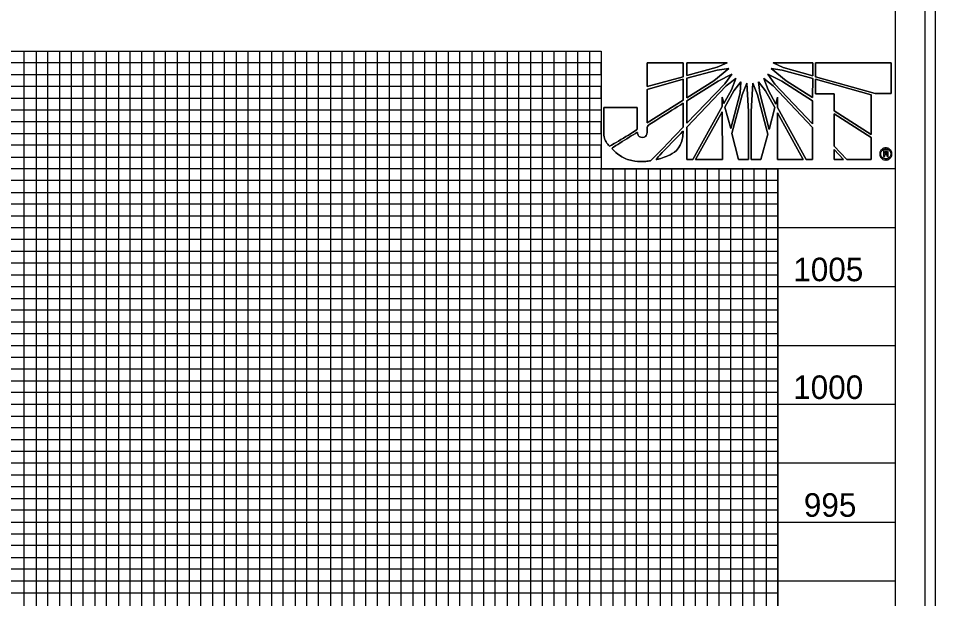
# Model space of a CAD drawing. Extents: x 0 to 4772457, y -312190 to 1506.
# Drawn here: x 2.184 to 2.833, y 0.492 to 0.902 of the extents above; entities that cross this region are included whole.
import ezdxf

# ---------------------------------------------------------------- set-up
doc = ezdxf.new("R2010")
doc.units = 0
for name, color, linetype in [('Exist Curb and Gutter', 7, 'Continuous'), ('Exist Mini Skip Lane Lines', 7, 'Continuous'), ('Legend CELL', 7, 'Continuous'), ('Old_Level_38', 7, 'Continuous'), ('Old_Level_57', 7, 'Continuous'), ('Old_Level_63', 7, 'Continuous')]:
    doc.layers.add(name, color=color, linetype=linetype)

# ---------------------------------------------------------------- blocks, each defined once
blk = doc.blocks.new('block 2_1')
at = {"layer": 'Exist Curb and Gutter'}
for p, q in [((0.10682, 0.1325), (0.10682, 0.14026)), ((0.10682, 0.14026), (0.11852, 0.14026)), ((0.11852, 0.14026), (0.11852, 0.13575)), ((0.11973, 0.13613), (0.11973, 0.14032)), ((0.11973, 0.14032), (0.1329, 0.14032)), ((0.12954, 0.13884), (0.11973, 0.13613)), ((0.11973, 0.13523), (0.12954, 0.13793)), ((0.13337, 0.13839), (0.12852, 0.13445)), ((0.1329, 0.14032), (0.12954, 0.13884)), ((0.12954, 0.13793), (0.13337, 0.13839)), ((0.14715, 0.13839), (0.15076, 0.13793)), ((0.15206, 0.13438), (0.14715, 0.13839)), ((0.15109, 0.13878), (0.14781, 0.14032)), ((0.14781, 0.14032), (0.16078, 0.14026)), ((0.15076, 0.13793), (0.16078, 0.13517)), ((0.16078, 0.13606), (0.15109, 0.13878)), ((0.16078, 0.14026), (0.16078, 0.13606)), ((0.16169, 0.1358), (0.16169, 0.14032)), ((0.16169, 0.14032), (0.18629, 0.14032)), ((0.18629, 0.14032), (0.18629, 0.13024)), ((0.11852, 0.13575), (0.10682, 0.1325)), ((0.10682, 0.13161), (0.11852, 0.1349)), ((0.11852, 0.1349), (0.11852, 0.12812)), ((0.11973, 0.12889), (0.11973, 0.13523)), ((0.12987, 0.13432), (0.13433, 0.13658)), ((0.13433, 0.13658), (0.13207, 0.13341)), ((0.13257, 0.13277), (0.13568, 0.13517)), ((0.13568, 0.13517), (0.13425, 0.13142)), ((0.14476, 0.13517), (0.14787, 0.13277)), ((0.14619, 0.13142), (0.14476, 0.13517)), ((0.14613, 0.13658), (0.15065, 0.13432)), ((0.14839, 0.13335), (0.14613, 0.13658)), ((0.16078, 0.13517), (0.16071, 0.12897)), ((0.16169, 0.13567), (0.16169, 0.1358)), ((0.18106, 0.13024), (0.16169, 0.13567)), ((0.16169, 0.13497), (0.17982, 0.1298)), ((0.16169, 0.1349), (0.16169, 0.13497)), ((0.16169, 0.13019), (0.16169, 0.1349)), ((0.10682, 0.12071), (0.10682, 0.13161)), ((0.12852, 0.13445), (0.11973, 0.12889)), ((0.11973, 0.12787), (0.12987, 0.13432)), ((0.13207, 0.13341), (0.11973, 0.12057)), ((0.11973, 0.11933), (0.13257, 0.13277)), ((0.13505, 0.13115), (0.13736, 0.13412)), ((0.13736, 0.13412), (0.13704, 0.13051)), ((0.13769, 0.12986), (0.13929, 0.1336)), ((0.13929, 0.1336), (0.1398, 0.12437)), ((0.14063, 0.12437), (0.14123, 0.1336)), ((0.14123, 0.1336), (0.14277, 0.12986)), ((0.1431, 0.13412), (0.14536, 0.13115)), ((0.14348, 0.13038), (0.1431, 0.13412)), ((0.14787, 0.13277), (0.16071, 0.11922)), ((0.16071, 0.12043), (0.14839, 0.13335)), ((0.15065, 0.13432), (0.16071, 0.12793)), ((0.16071, 0.12897), (0.15206, 0.13438)), ((0.1318, 0.12696), (0.13122, 0.12908)), ((0.13122, 0.12908), (0.13122, 0.126)), ((0.13425, 0.13142), (0.1318, 0.12696)), ((0.13213, 0.12586), (0.13505, 0.13115)), ((0.13704, 0.13051), (0.134, 0.11883)), ((0.13439, 0.11721), (0.13769, 0.12986)), ((0.14277, 0.12986), (0.14613, 0.11702)), ((0.14652, 0.11856), (0.14348, 0.13038)), ((0.14536, 0.13115), (0.14839, 0.12567)), ((0.1487, 0.12677), (0.14619, 0.13142)), ((0.1493, 0.12908), (0.1487, 0.12677)), ((0.1493, 0.12567), (0.1493, 0.12908)), ((0.1677, 0.13019), (0.16169, 0.13019)), ((0.1677, 0.12457), (0.1677, 0.13019)), ((0.17982, 0.1298), (0.17982, 0.11688)), ((0.18629, 0.13024), (0.18106, 0.13024)), ((0.11852, 0.12812), (0.10682, 0.12071)), ((0.11973, 0.12057), (0.11973, 0.12787)), ((0.13122, 0.126), (0.12167, 0.10871)), ((0.134, 0.11883), (0.13213, 0.12586)), ((0.14839, 0.12567), (0.14652, 0.11856)), ((0.15864, 0.10871), (0.1493, 0.12567)), ((0.16071, 0.12793), (0.16071, 0.12043)), ((0.12257, 0.10871), (0.13122, 0.12432)), ((0.13122, 0.12432), (0.1313, 0.10871)), ((0.1398, 0.12437), (0.1398, 0.10877)), ((0.14063, 0.10877), (0.14063, 0.12437)), ((0.1493, 0.10877), (0.1493, 0.12399)), ((0.1493, 0.12399), (0.15768, 0.10877)), ((0.17982, 0.11688), (0.1677, 0.12457)), ((0.1677, 0.1236), (0.17982, 0.11597)), ((0.1677, 0.11314), (0.1677, 0.1236)), ((0.11973, 0.10871), (0.11973, 0.11933)), ((0.13659, 0.10877), (0.13439, 0.11721)), ((0.14613, 0.11702), (0.14387, 0.10877)), ((0.16071, 0.11922), (0.16071, 0.10871)), ((0.17982, 0.11597), (0.17982, 0.10871)), ((0.17189, 0.10871), (0.1677, 0.11314)), ((0.1677, 0.10871), (0.1677, 0.112)), ((0.1677, 0.112), (0.17073, 0.10871)), ((0.12167, 0.10871), (0.11973, 0.10871)), ((0.1313, 0.10871), (0.12257, 0.10871)), ((0.1398, 0.10877), (0.13659, 0.10877)), ((0.14387, 0.10877), (0.14063, 0.10877)), ((0.15768, 0.10877), (0.1493, 0.10877)), ((0.16071, 0.10871), (0.15864, 0.10871)), ((0.17073, 0.10871), (0.1677, 0.10871)), ((0.17982, 0.10871), (0.17189, 0.10871))]:
    blk.add_line(p, q, dxfattribs=at)
for points in [[(0.10682, 0.1325), (0.11852, 0.13575), (0.11852, 0.14026), (0.10682, 0.14026), (0.10682, 0.1325)], [(0.12954, 0.13884), (0.1329, 0.14032), (0.11973, 0.14032), (0.11973, 0.13613), (0.12954, 0.13884)], [(0.11973, 0.13523), (0.11973, 0.12889), (0.12852, 0.13445), (0.13337, 0.13839), (0.12954, 0.13793), (0.11973, 0.13523)], [(0.14715, 0.13839), (0.15206, 0.13438), (0.16071, 0.12897), (0.16078, 0.13517), (0.15076, 0.13793), (0.14715, 0.13839)], [(0.15109, 0.13878), (0.16078, 0.13606), (0.16078, 0.14026), (0.14781, 0.14032), (0.15109, 0.13878)], [(0.18629, 0.14032), (0.16169, 0.14032), (0.16169, 0.1358), (0.16169, 0.13567), (0.18106, 0.13024), (0.18629, 0.13024), (0.18629, 0.14032)], [(0.10682, 0.12071), (0.11852, 0.12812), (0.11852, 0.1349), (0.10682, 0.13161), (0.10682, 0.12071)], [(0.11973, 0.12787), (0.11973, 0.12057), (0.13207, 0.13341), (0.13433, 0.13658), (0.12987, 0.13432), (0.11973, 0.12787)], [(0.13568, 0.13517), (0.13257, 0.13277), (0.11973, 0.11933), (0.11973, 0.10871), (0.12167, 0.10871), (0.13122, 0.126), (0.13122, 0.12908), (0.1318, 0.12696), (0.13425, 0.13142), (0.13568, 0.13517)], [(0.14476, 0.13517), (0.14619, 0.13142), (0.1487, 0.12677), (0.1493, 0.12908), (0.1493, 0.12567), (0.15864, 0.10871), (0.16071, 0.10871), (0.16071, 0.11922), (0.14787, 0.13277), (0.14476, 0.13517)], [(0.14613, 0.13658), (0.14839, 0.13335), (0.16071, 0.12043), (0.16071, 0.12793), (0.15065, 0.13432), (0.14613, 0.13658)], [(0.16169, 0.13497), (0.16169, 0.1349), (0.16169, 0.13019), (0.1677, 0.13019), (0.1677, 0.12457), (0.17982, 0.11688), (0.17982, 0.1298), (0.16169, 0.13497)], [(0.13736, 0.13412), (0.13505, 0.13115), (0.13213, 0.12586), (0.134, 0.11883), (0.13704, 0.13051), (0.13736, 0.13412)], [(0.13769, 0.12986), (0.13439, 0.11721), (0.13659, 0.10877), (0.1398, 0.10877), (0.1398, 0.12437), (0.13929, 0.1336), (0.13769, 0.12986)], [(0.14123, 0.1336), (0.14063, 0.12437), (0.14063, 0.10877), (0.14387, 0.10877), (0.14613, 0.11702), (0.14277, 0.12986), (0.14123, 0.1336)], [(0.1431, 0.13412), (0.14348, 0.13038), (0.14652, 0.11856), (0.14839, 0.12567), (0.14536, 0.13115), (0.1431, 0.13412)], [(0.12257, 0.10871), (0.1313, 0.10871), (0.13122, 0.12432), (0.12257, 0.10871)], [(0.1493, 0.10877), (0.15768, 0.10877), (0.1493, 0.12399), (0.1493, 0.10877)], [(0.1677, 0.1236), (0.1677, 0.11314), (0.17189, 0.10871), (0.17982, 0.10871), (0.17982, 0.11597), (0.1677, 0.1236), (0.1677, 0.1236)], [(0.1677, 0.10871), (0.1677, 0.10871), (0.17073, 0.10871), (0.1677, 0.112), (0.1677, 0.10871)], [(0.18456, 0.11147), (0.18383, 0.11147), (0.18383, 0.10968), (0.18424, 0.10968), (0.18424, 0.11038), (0.18456, 0.11038), (0.18456, 0.1107), (0.18424, 0.1107), (0.18424, 0.11113), (0.18456, 0.11113), (0.18456, 0.11147)], [(0.18456, 0.11147), (0.18383, 0.11147), (0.18383, 0.10968), (0.18424, 0.10968), (0.18424, 0.11038), (0.18456, 0.11038)], [(0.18456, 0.1107), (0.18424, 0.1107), (0.18424, 0.11113), (0.18456, 0.11113)]]:
    blk.add_lwpolyline(points, dxfattribs=at)
for points in [[(0.10346, 0.12573), (0.10346, 0.12573), (0.09263, 0.12573), (0.09263, 0.12573), (0.09263, 0.12573), (0.09263, 0.11895), (0.09263, 0.11895), (0.09263, 0.11895), (0.09263, 0.11823), (0.09263, 0.11823), (0.09263, 0.11611), (0.09332, 0.11443), (0.09456, 0.11302), (0.09456, 0.11302), (0.10346, 0.11843), (0.10346, 0.11856), (0.10346, 0.11856), (0.10346, 0.12573), (0.10346, 0.12573)], [(0.10346, 0.12573), (0.10346, 0.12573), (0.10346, 0.11856), (0.10346, 0.11856), (0.10346, 0.11843), (0.09456, 0.11302), (0.09456, 0.11302), (0.09332, 0.11443), (0.09263, 0.11611), (0.09263, 0.11823), (0.09263, 0.11823), (0.09263, 0.11895), (0.09263, 0.11895), (0.09263, 0.11895), (0.09263, 0.12573), (0.09263, 0.12573), (0.09263, 0.12573), (0.10346, 0.12573), (0.10346, 0.12573)], [(0.10514, 0.11597), (0.10444, 0.11597), (0.10384, 0.11636), (0.10359, 0.11765), (0.10359, 0.11765), (0.09519, 0.11246), (0.09519, 0.11246), (0.09778, 0.10974), (0.10191, 0.10812), (0.10541, 0.10812), (0.10632, 0.10812), (0.10701, 0.10819), (0.10798, 0.10839), (0.10798, 0.10839), (0.11852, 0.11928), (0.11852, 0.11928), (0.11852, 0.11928), (0.11852, 0.12715), (0.11852, 0.12715), (0.11852, 0.12715), (0.10682, 0.11972), (0.10682, 0.11972), (0.10682, 0.11677), (0.1061, 0.11597), (0.10514, 0.11597)], [(0.10514, 0.11597), (0.1061, 0.11597), (0.10682, 0.11677), (0.10682, 0.11972), (0.10682, 0.11972), (0.11852, 0.12715), (0.11852, 0.12715), (0.11852, 0.12715), (0.11852, 0.11928), (0.11852, 0.11928), (0.11852, 0.11928), (0.10798, 0.10839), (0.10798, 0.10839), (0.10701, 0.10819), (0.10632, 0.10812), (0.10541, 0.10812), (0.10191, 0.10812), (0.09778, 0.10974), (0.09519, 0.11246), (0.09519, 0.11246), (0.10359, 0.11765), (0.10359, 0.11765), (0.10384, 0.11636), (0.10444, 0.11597), (0.10514, 0.11597)], [(0.11852, 0.11804), (0.11852, 0.11804), (0.1094, 0.10864), (0.1094, 0.10864), (0.11386, 0.10974), (0.11831, 0.11269), (0.11852, 0.11804)], [(0.11852, 0.11804), (0.11831, 0.11269), (0.11386, 0.10974), (0.1094, 0.10864), (0.1094, 0.10864), (0.11852, 0.11804), (0.11852, 0.11804)], [(0.18456, 0.10859), (0.18403, 0.10859), (0.18355, 0.10878), (0.18316, 0.10917), (0.18277, 0.10955), (0.18258, 0.11002), (0.18258, 0.11057), (0.18258, 0.11113), (0.18277, 0.1116), (0.18316, 0.11195), (0.18355, 0.11233), (0.18401, 0.11252), (0.18456, 0.11252), (0.18456, 0.11252), (0.18456, 0.11215), (0.18456, 0.11215), (0.18412, 0.11215), (0.18375, 0.112), (0.18344, 0.11171), (0.18313, 0.1114), (0.18297, 0.11101), (0.18297, 0.11057), (0.18297, 0.11013), (0.18313, 0.10974), (0.18344, 0.10943), (0.18375, 0.10913), (0.18412, 0.10898), (0.18456, 0.10898), (0.18456, 0.10898), (0.18456, 0.10859), (0.18456, 0.10859), (0.18456, 0.10859), (0.18456, 0.10859), (0.18456, 0.10859)], [(0.18456, 0.11252), (0.18401, 0.11252), (0.18355, 0.11233), (0.18316, 0.11195), (0.18277, 0.1116), (0.18258, 0.11113), (0.18258, 0.11057), (0.18258, 0.11002), (0.18277, 0.10955), (0.18316, 0.10917), (0.18355, 0.10878), (0.18403, 0.10859), (0.18456, 0.10859)], [(0.18456, 0.10898), (0.18412, 0.10898), (0.18375, 0.10913), (0.18344, 0.10943), (0.18313, 0.10974), (0.18297, 0.11013), (0.18297, 0.11057), (0.18297, 0.11101), (0.18313, 0.1114), (0.18344, 0.11171), (0.18375, 0.112), (0.18412, 0.11215), (0.18456, 0.11215)], [(0.18656, 0.11057), (0.18656, 0.11002), (0.18637, 0.10955), (0.18599, 0.10916), (0.1856, 0.10878), (0.18513, 0.10859), (0.18458, 0.10859), (0.18458, 0.10859), (0.18458, 0.10859), (0.18456, 0.10859), (0.18456, 0.10859), (0.18456, 0.10898), (0.18456, 0.10898), (0.18458, 0.10898), (0.18458, 0.10898), (0.18458, 0.10898), (0.18502, 0.10898), (0.18539, 0.10913), (0.1857, 0.10943), (0.18601, 0.10974), (0.18617, 0.11013), (0.18617, 0.11057), (0.18617, 0.11101), (0.18601, 0.1114), (0.1857, 0.11171), (0.18539, 0.112), (0.18502, 0.11215), (0.18456, 0.11215), (0.18456, 0.11215), (0.18456, 0.11252), (0.18456, 0.11252), (0.18512, 0.11252), (0.18559, 0.11233), (0.18598, 0.11195), (0.18637, 0.1116), (0.18656, 0.11113), (0.18656, 0.11057), (0.18656, 0.11057), (0.18656, 0.11057), (0.18656, 0.11057)], [(0.18656, 0.11057), (0.18656, 0.11113), (0.18637, 0.1116), (0.18598, 0.11195), (0.18559, 0.11233), (0.18512, 0.11252), (0.18456, 0.11252)], [(0.18456, 0.11215), (0.18502, 0.11215), (0.18539, 0.112), (0.1857, 0.11171), (0.18601, 0.1114), (0.18617, 0.11101), (0.18617, 0.11057), (0.18617, 0.11013), (0.18601, 0.10974), (0.1857, 0.10943), (0.18539, 0.10913), (0.18502, 0.10898), (0.18458, 0.10898), (0.18458, 0.10898), (0.18458, 0.10898), (0.18456, 0.10898)], [(0.18456, 0.11038), (0.18456, 0.11038), (0.18456, 0.1107), (0.18456, 0.1107), (0.18456, 0.1107), (0.18458, 0.1107), (0.18458, 0.1107), (0.18484, 0.1107), (0.18497, 0.11078), (0.18497, 0.11093), (0.18497, 0.11106), (0.18485, 0.11113), (0.18461, 0.11113), (0.18461, 0.11113), (0.18456, 0.11113), (0.18456, 0.11113), (0.18456, 0.11113), (0.18456, 0.11147), (0.18456, 0.11147), (0.18456, 0.11147), (0.18468, 0.11147), (0.18468, 0.11147), (0.18513, 0.11147), (0.18536, 0.11129), (0.18536, 0.11093), (0.18536, 0.11077), (0.18529, 0.11064), (0.18515, 0.11054), (0.18526, 0.11048), (0.18533, 0.11033), (0.18534, 0.1101), (0.18534, 0.1101), (0.18534, 0.11), (0.18534, 0.11), (0.18534, 0.11), (0.18536, 0.10994), (0.18536, 0.10994), (0.18536, 0.10994), (0.18536, 0.10987), (0.18536, 0.10987), (0.18536, 0.10987), (0.18541, 0.10968), (0.18541, 0.10968), (0.18541, 0.10968), (0.18503, 0.10968), (0.18503, 0.10968), (0.18499, 0.10978), (0.18495, 0.10987), (0.18495, 0.11), (0.18495, 0.11017), (0.18494, 0.11026), (0.18489, 0.11031), (0.18484, 0.11034), (0.18474, 0.11038), (0.18458, 0.11038), (0.18458, 0.11038), (0.18456, 0.11038), (0.18456, 0.11038)], [(0.18456, 0.11038), (0.18456, 0.11038), (0.18458, 0.11038), (0.18458, 0.11038), (0.18474, 0.11038), (0.18484, 0.11034), (0.18489, 0.11031), (0.18494, 0.11026), (0.18495, 0.11017), (0.18495, 0.11), (0.18495, 0.10987), (0.18499, 0.10978), (0.18503, 0.10968), (0.18503, 0.10968), (0.18541, 0.10968), (0.18541, 0.10968), (0.18541, 0.10968), (0.18536, 0.10987), (0.18536, 0.10987), (0.18536, 0.10987), (0.18536, 0.10994), (0.18536, 0.10994), (0.18536, 0.10994), (0.18534, 0.11), (0.18534, 0.11), (0.18534, 0.11), (0.18534, 0.1101), (0.18534, 0.1101), (0.18533, 0.11033), (0.18526, 0.11048), (0.18515, 0.11054), (0.18529, 0.11064), (0.18536, 0.11077), (0.18536, 0.11093), (0.18536, 0.11129), (0.18513, 0.11147), (0.18468, 0.11147), (0.18468, 0.11147), (0.18456, 0.11147), (0.18456, 0.11147)], [(0.18456, 0.11113), (0.18456, 0.11113), (0.18461, 0.11113), (0.18461, 0.11113), (0.18485, 0.11113), (0.18497, 0.11106), (0.18497, 0.11093), (0.18497, 0.11078), (0.18484, 0.1107), (0.18458, 0.1107), (0.18458, 0.1107), (0.18456, 0.1107), (0.18456, 0.1107)], [(0.18456, 0.10859), (0.18458, 0.10859), (0.18458, 0.10859), (0.18458, 0.10859), (0.18513, 0.10859), (0.1856, 0.10878), (0.18599, 0.10916), (0.18637, 0.10955), (0.18656, 0.11002), (0.18656, 0.11057)]]:
    blk.add_open_spline(points, degree=3, dxfattribs=at)

msp = doc.modelspace()

# ---------------------------------------------------------------- linework, layer by layer
at = {"layer": 'Exist Mini Skip Lane Lines'}
for p, q in [((0.30499, 0.8375), (2.59666, 0.8375)), ((2.80499, 0.75416), (0.30499, 0.75416)), ((0.30499, 0.67083), (2.80499, 0.67083)), ((2.80499, 0.5875), (0.30499, 0.5875)), ((0.30499, 0.50416), (2.80499, 0.50416))]:
    msp.add_line(p, q, dxfattribs=at)
for points in [[(2.26333, 0.0875), (2.26333, 0.87916), (2.34666, 0.87916), (2.34666, 0.0875)], [(2.42999, 0.0875), (2.42999, 0.87916), (2.51333, 0.87916), (2.51333, 0.0875)], [(2.59666, 0.0875), (2.59666, 0.79583), (2.67999, 0.79583), (2.67999, 0.0875)]]:
    msp.add_lwpolyline(points, dxfattribs=at)
at = {"layer": 'Old_Level_38'}
for points in [[(0.30499, 0.87916), (2.59666, 0.87916)], [(2.22166, 0.0875), (2.22166, 0.87916), (2.30499, 0.87916), (2.30499, 0.0875)], [(2.38833, 0.0875), (2.38833, 0.87916), (2.47166, 0.87916), (2.47166, 0.0875)], [(2.55499, 0.0875), (2.55499, 0.87916), (2.59666, 0.87916), (2.59666, 0.79583), (2.63833, 0.79583), (2.63833, 0.0875)], [(2.80499, 0.79583), (0.30499, 0.79583), (0.30499, 0.7125), (2.80499, 0.7125)], [(2.72166, 0.0875), (2.72166, 0.79583)], [(2.80499, 0.62916), (0.30499, 0.62916), (0.30499, 0.54583), (2.80499, 0.54583)]]:
    msp.add_lwpolyline(points, dxfattribs=at)
at = {"layer": 'Old_Level_57'}
for points in [[(2.18833, 0.0875), (2.18833, 0.87916), (2.19666, 0.87916), (2.19666, 0.0875)], [(2.20499, 0.0875), (2.20499, 0.87916), (2.21333, 0.87916), (2.21333, 0.0875)], [(2.22999, 0.0875), (2.22999, 0.87916), (2.23833, 0.87916), (2.23833, 0.0875)], [(2.24666, 0.0875), (2.24666, 0.87916), (2.25499, 0.87916), (2.25499, 0.0875)], [(2.27166, 0.0875), (2.27166, 0.87916), (2.27999, 0.87916), (2.27999, 0.0875)], [(2.28833, 0.0875), (2.28833, 0.87916), (2.29666, 0.87916), (2.29666, 0.0875)], [(2.31333, 0.0875), (2.31333, 0.87916), (2.32166, 0.87916), (2.32166, 0.0875)], [(2.32999, 0.0875), (2.32999, 0.87916), (2.33833, 0.87916), (2.33833, 0.0875)], [(2.35499, 0.0875), (2.35499, 0.87916), (2.36333, 0.87916), (2.36333, 0.0875)], [(2.37166, 0.0875), (2.37166, 0.87916), (2.37999, 0.87916), (2.37999, 0.0875)], [(2.39666, 0.0875), (2.39666, 0.87916), (2.40499, 0.87916), (2.40499, 0.0875)], [(2.41333, 0.0875), (2.41333, 0.87916), (2.42166, 0.87916), (2.42166, 0.0875)], [(2.43833, 0.0875), (2.43833, 0.87916), (2.44666, 0.87916), (2.44666, 0.0875)], [(2.45499, 0.0875), (2.45499, 0.87916), (2.46333, 0.87916), (2.46333, 0.0875)], [(2.47999, 0.0875), (2.47999, 0.87916), (2.48833, 0.87916), (2.48833, 0.0875)], [(2.49666, 0.0875), (2.49666, 0.87916), (2.50499, 0.87916), (2.50499, 0.0875)], [(2.52166, 0.0875), (2.52166, 0.87916), (2.52999, 0.87916), (2.52999, 0.0875)], [(2.53833, 0.0875), (2.53833, 0.87916), (2.54666, 0.87916), (2.54666, 0.0875)], [(2.56333, 0.0875), (2.56333, 0.87916), (2.57166, 0.87916), (2.57166, 0.0875)], [(2.57999, 0.0875), (2.57999, 0.87916), (2.58833, 0.87916), (2.58833, 0.0875)], [(0.38833, 0.8625), (2.59666, 0.8625), (2.59666, 0.87083), (0.38833, 0.87083)], [(0.38833, 0.84583), (2.59666, 0.84583), (2.59666, 0.85416), (0.38833, 0.85416)], [(0.38833, 0.82083), (2.59666, 0.82083), (2.59666, 0.82916), (0.38833, 0.82916)], [(0.38833, 0.80416), (2.59666, 0.80416), (2.59666, 0.8125), (0.38833, 0.8125)], [(2.60499, 0.0875), (2.60499, 0.79583), (2.61333, 0.79583), (2.61333, 0.0875)], [(2.62166, 0.0875), (2.62166, 0.79583), (2.62999, 0.79583), (2.62999, 0.0875)], [(2.64666, 0.0875), (2.64666, 0.79583), (2.65499, 0.79583), (2.65499, 0.0875)], [(2.66333, 0.0875), (2.66333, 0.79583), (2.67166, 0.79583), (2.67166, 0.0875)], [(2.68833, 0.0875), (2.68833, 0.79583), (2.69666, 0.79583), (2.69666, 0.0875)], [(2.70499, 0.0875), (2.70499, 0.79583), (2.71333, 0.79583), (2.71333, 0.0875)], [(0.38833, 0.77916), (2.72166, 0.77916), (2.72166, 0.7875), (0.38833, 0.7875)], [(0.38833, 0.7625), (2.72166, 0.7625), (2.72166, 0.77083), (0.38833, 0.77083)], [(0.38833, 0.7375), (2.72166, 0.7375), (2.72166, 0.74583), (0.38833, 0.74583)], [(0.38833, 0.72083), (2.72166, 0.72083), (2.72166, 0.72916), (0.38833, 0.72916)], [(0.38833, 0.70416), (2.72166, 0.70416)], [(0.38833, 0.6875), (2.72166, 0.6875), (2.72166, 0.69583), (0.38833, 0.69583)], [(0.38833, 0.6625), (2.72166, 0.6625), (2.72166, 0.67916), (0.38833, 0.67916)], [(0.38833, 0.64583), (2.72166, 0.64583), (2.72166, 0.65416), (0.38833, 0.65416)], [(0.38833, 0.62083), (2.72166, 0.62083), (2.72166, 0.6375), (0.38833, 0.6375)], [(0.38833, 0.60416), (2.72166, 0.60416), (2.72166, 0.6125), (0.38833, 0.6125)], [(0.38833, 0.57916), (2.72166, 0.57916), (2.72166, 0.59583), (0.38833, 0.59583)], [(0.38833, 0.5625), (2.72166, 0.5625), (2.72166, 0.57083), (0.38833, 0.57083)], [(0.38833, 0.5375), (2.72166, 0.5375), (2.72166, 0.55416), (0.38833, 0.55416)], [(0.38833, 0.52083), (2.72166, 0.52083), (2.72166, 0.52916), (0.38833, 0.52916)], [(0.38833, 0.49583), (2.72166, 0.49583), (2.72166, 0.5125), (0.38833, 0.5125)]]:
    msp.add_lwpolyline(points, dxfattribs=at)
at = {"layer": 'Old_Level_63'}
for points in [[(0.02749, 0.00833), (2.83333, 0.00833), (2.83333, 1.83333), (0.02749, 1.83333)], [(0.04916, 0.04166), (2.82583, 0.04166), (2.82583, 1.8), (0.04916, 1.8)], [(2.80499, 1.79583), (0.30499, 1.79583), (0.30499, 0.04583), (2.80499, 0.04583)], [(0.38833, 0.87916), (2.59666, 0.87916), (2.59666, 0.79583), (2.72166, 0.79583), (2.72166, 0.0875), (0.38833, 0.0875)]]:
    msp.add_lwpolyline(points, close=True, dxfattribs=at)

# ---------------------------------------------------------------- block references
at = {"layer": 'Legend CELL', "xscale": 2.170686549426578, "yscale": 2.170686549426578}
msp.add_blockref('block 2_1', (2.3974, 0.56633), dxfattribs=at)

# ---------------------------------------------------------------- texts
at = {"layer": 'Old_Level_63'}
for s, p in [('1005', (2.73255, 0.71627)), ('1000', (2.73249, 0.63294)), ('995', (2.74005, 0.54961))]:
    msp.add_text(s, height=0.016667, dxfattribs=at).set_placement(p)

doc.saveas('drawing.dxf')
